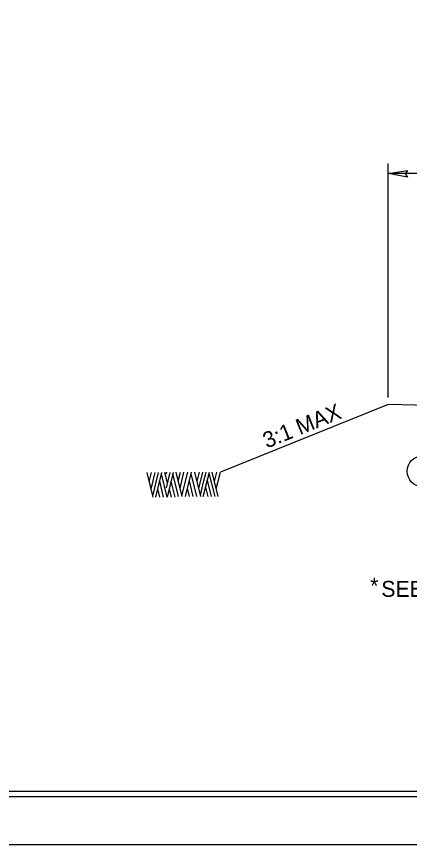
# Model space of a CAD drawing. Extents: x 573748 to 574632, y -54663 to -53209.
# Drawn here: x 574080.7 to 574117.6, y -53428.7 to -53351 of the extents above; entities that cross this region are included whole.
import ezdxf

# ---------------------------------------------------------------- set-up
doc = ezdxf.new("R2010")
doc.units = 0
for name, color, linetype in [('Prop Dimension', 7, 'Continuous'), ('Prop Dimension Text', 7, 'Continuous'), ('Prop Terminator CELL', 7, 'Continuous'), ('Sheet Cutting Line CELL', 7, 'Continuous'), ('Sheet Plot Border Inside CELL', 7, 'Continuous'), ('Sheet Plot Border Outside CELL', 7, 'Continuous'), ('Sheet Typical CELL', 7, 'Continuous'), ('Typical Hinge Slope Arterial CELL', 7, 'Continuous'), ('Typical ID Circle CELL', 7, 'Continuous'), ('Typical Pavement Slope CELL', 7, 'Continuous'), ('Typical Slope Point Local CELL', 7, 'Continuous'), ('Typical Text General CELL', 7, 'Continuous')]:
    doc.layers.add(name, color=color, linetype=linetype)

msp = doc.modelspace()

# ---------------------------------------------------------------- linework, layer by layer
at = {"layer": 'Prop Dimension'}
for p, q in [((574115.581, -53386.757), (574115.581, -53364.825)), ((574126.334, -53365.76), (574115.581, -53365.76))]:
    msp.add_line(p, q, dxfattribs=at)
at = {"layer": 'Prop Terminator CELL'}
msp.add_lwpolyline([(574117.378, -53366.093), (574115.581, -53365.76), (574117.396, -53365.463), (574117.161, -53365.78)], close=True, dxfattribs=at)
at = {"layer": 'Sheet Cutting Line CELL'}
msp.add_line((573944.171, -53428.71), (574280.971, -53428.71), dxfattribs=at)
at = {"layer": 'Sheet Plot Border Inside CELL'}
msp.add_lwpolyline([(574280.071, -53213.2), (573946.771, -53213.2), (573946.771, -53424.22), (574280.071, -53424.22)], close=True, dxfattribs=at)
at = {"layer": 'Sheet Plot Border Outside CELL'}
msp.add_lwpolyline([(574280.971, -53208.71), (573944.171, -53208.71), (573944.171, -53428.71), (574280.971, -53428.71)], close=True, dxfattribs=at)
at = {"layer": 'Sheet Typical CELL'}
msp.add_lwpolyline([(574277.571, -53213.71), (573977.571, -53213.71), (573977.571, -53423.71), (574277.571, -53423.71)], close=True, dxfattribs=at)
at = {"layer": 'Typical Hinge Slope Arterial CELL'}
msp.add_line((574115.581, -53387.42), (574099.816, -53393.789), dxfattribs=at)
at = {"layer": 'Typical ID Circle CELL'}
msp.add_circle((574118.802, -53393.69), 1.443, dxfattribs=at)
at = {"layer": 'Typical Pavement Slope CELL'}
msp.add_line((574125.235, -53387.633), (574115.581, -53387.42), dxfattribs=at)
at = {"layer": 'Typical Slope Point Local CELL'}
for p, q in [((574093.49, -53396.107), (574092.927, -53393.811)), ((574093.139, -53394.689), (574093.352, -53393.818)), ((574093.309, -53395.376), (574093.694, -53393.818)), ((574093.474, -53396.033), (574094.021, -53393.818)), ((574093.75, -53396.107), (574094.32, -53393.818)), ((574094.832, -53396.107), (574094.293, -53393.936)), ((574094.844, -53394.785), (574094.604, -53393.818)), ((574094.714, -53393.892), (574094.742, -53393.789)), ((574094.757, -53395.25), (574095.112, -53393.818)), ((574094.757, -53393.929), (574094.781, -53393.818)), ((574094.84, -53396.107), (574095.411, -53393.818)), ((574095.879, -53396.07), (574095.344, -53393.899)), ((574096.218, -53396.07), (574095.655, -53393.789)), ((574095.868, -53394.63), (574096.072, -53393.789)), ((574096.029, -53395.295), (574096.399, -53393.789)), ((574096.202, -53396.003), (574096.75, -53393.789)), ((574096.537, -53396.07), (574097.104, -53393.789)), ((574097.616, -53396.07), (574097.076, -53393.892)), ((574097.982, -53396.07), (574097.419, -53393.789)), ((574097.631, -53394.66), (574097.844, -53393.789)), ((574097.797, -53395.317), (574098.179, -53393.789)), ((574098.214, -53394.852), (574098.474, -53393.789)), ((574098.214, -53396.07), (574098.781, -53393.789)), ((574099.313, -53396.07), (574098.765, -53393.855)), ((574099.616, -53396.07), (574099.053, -53393.774)), ((574099.261, -53394.652), (574099.474, -53393.789)), ((574099.435, -53395.339), (574099.816, -53393.789)), ((574094.482, -53396.107), (574094.12, -53394.623)), ((574094.82, -53394.66), (574094.844, -53394.571)), ((574095.572, -53396.107), (574095.21, -53394.623)), ((574097.269, -53396.07), (574096.903, -53394.586)), ((574097.946, -53395.929), (574098.214, -53394.852)), ((574098.978, -53396.07), (574098.6, -53394.512)), ((574094.128, -53396.107), (574093.942, -53395.339)), ((574095.218, -53396.107), (574095.033, -53395.339)), ((574096.923, -53396.07), (574096.734, -53395.28)), ((574098.659, -53396.07), (574098.439, -53395.169))]:
    msp.add_line(p, q, dxfattribs=at)

# ---------------------------------------------------------------- texts
at = {"layer": 'Prop Dimension Text'}
msp.add_text('3:1 MAX', height=1.5, rotation=21.99879, dxfattribs=at).set_placement((574104.182, -53391.566))
msp.add_text('*', height=1.5, dxfattribs=at).set_placement((574113.883, -53405.186))
at = {"layer": 'Typical Text General CELL'}
msp.add_text('SEE PLANS FOR LIMITS OF CONC. ISLAND', height=1.5, dxfattribs=at).set_placement((574114.927, -53405.478))

doc.saveas('drawing.dxf')
